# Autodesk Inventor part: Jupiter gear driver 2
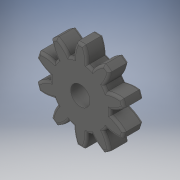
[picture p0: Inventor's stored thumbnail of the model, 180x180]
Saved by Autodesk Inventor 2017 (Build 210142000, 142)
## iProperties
Created: 2016-05
Part Number: Jupiter gear driver 2
Material: Generic
Document SubType Name: Modeling
Designer: Stan
Density: 1 g/cm^3
Appearance: Gray
Author: Stan
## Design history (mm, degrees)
sketch "Sketch1"
  geometry: A1 r 11.354 centre (-11.946, -5.594) between (-8.555, 5.242) and (-13.611, 5.638); A2 r 11.354 centre (-11.946, -5.594) between (-8.555, 5.242) and (-13.611, 5.638); A3 r 11.354 centre (1.628, 13.089) between (-9.568, 11.202) and (-7.629, 6.516); A4 r 11.354 centre (1.628, 13.089) between (-9.568, 11.202) and (-7.629, 6.516); A5 r 11.354 centre (-6.376, -11.547) between (-10.002, -0.787) and (-14.325, -3.439); A6 r 11.354 centre (-6.376, -11.547) between (-10.002, -0.787) and (-14.325, -3.439); A7 r 11.354 centre (-6.376, 11.547) between (-14.325, 3.439) and (-10.002, 0.787); A8 r 11.354 centre (-6.376, 11.547) between (-14.325, 3.439) and (-10.002, 0.787); A9 r 11.354 centre (1.628, -13.089) between (-7.629, -6.516) and (-9.568, -11.202); A10 r 11.354 centre (1.628, -13.089) between (-7.629, -6.516) and (-9.568, -11.202); A11 r 11.354 centre (-11.946, 5.594) between (-13.611, -5.638) and (-8.555, -5.242); A12 r 11.354 centre (-11.946, 5.594) between (-13.611, -5.638) and (-8.555, -5.242); A13 r 11.354 centre (9.011, -9.632) between (-2.342, -9.756) and (-1.156, -14.687); A14 r 11.354 centre (9.011, -9.632) between (-2.342, -9.756) and (-1.156, -14.687); A15 r 11.354 centre (-12.952, -2.496) between (-7.697, -12.561) and (-3.839, -9.269); A16 r 11.354 centre (-12.952, -2.496) between (-7.697, -12.561) and (-3.839, -9.269); A17 r 11.354 centre (12.952, -2.496) between (3.839, -9.269) and (7.697, -12.561); A18 r 11.354 centre (12.952, -2.496) between (3.839, -9.269) and (7.697, -12.561); A19 r 11.354 centre (-9.011, -9.632) between (1.156, -14.687) and (2.342, -9.756); A20 r 11.354 centre (-9.011, -9.632) between (1.156, -14.687) and (2.342, -9.756); A21 r 11.354 centre (11.946, 5.594) between (8.555, -5.242) and (13.611, -5.638); A22 r 11.354 centre (11.946, 5.594) between (8.555, -5.242) and (13.611, -5.638); A23 r 11.354 centre (-1.628, -13.089) between (9.568, -11.202) and (7.629, -6.516); A24 r 11.354 centre (-1.628, -13.089) between (9.568, -11.202) and (7.629, -6.516); A25 r 11.354 centre (6.376, 11.547) between (10.002, 0.787) and (14.325, 3.439); A26 r 11.354 centre (6.376, 11.547) between (10.002, 0.787) and (14.325, 3.439); A27 r 11.354 centre (6.376, -11.547) between (14.325, -3.439) and (10.002, -0.787); A28 r 11.354 centre (6.376, -11.547) between (14.325, -3.439) and (10.002, -0.787); A29 r 11.354 centre (-1.628, 13.089) between (7.629, 6.516) and (9.568, 11.202); A30 r 11.354 centre (-1.628, 13.089) between (7.629, 6.516) and (9.568, 11.202); A31 r 11.354 centre (11.946, -5.594) between (13.611, 5.638) and (8.555, 5.242); A32 r 11.354 centre (11.946, -5.594) between (13.611, 5.638) and (8.555, 5.242); A33 r 11.354 centre (-9.011, 9.632) between (2.342, 9.756) and (1.156, 14.687); A34 r 11.354 centre (-9.011, 9.632) between (2.342, 9.756) and (1.156, 14.687); A35 r 11.354 centre (12.952, 2.496) between (7.697, 12.561) and (3.839, 9.269); A36 r 11.354 centre (12.952, 2.496) between (7.697, 12.561) and (3.839, 9.269); A37 r 11.354 centre (1.628, 13.089) between (-9.568, 11.202) and (-7.629, 6.516); A38 r 11.354 centre (-11.946, -5.594) between (-8.555, 5.242) and (-13.611, 5.638); A39 r 11.354 centre (-6.376, 11.547) between (-14.325, 3.439) and (-10.002, 0.787); A40 r 11.354 centre (-6.376, -11.547) between (-10.002, -0.787) and (-14.325, -3.439); A41 r 11.354 centre (-11.946, 5.594) between (-13.611, -5.638) and (-8.555, -5.242); A42 r 11.354 centre (1.628, -13.089) between (-7.629, -6.516) and (-9.568, -11.202); A43 r 11.354 centre (-12.952, -2.496) between (-7.697, -12.561) and (-3.839, -9.269); A44 r 11.354 centre (9.011, -9.632) between (-2.342, -9.756) and (-1.156, -14.687); A45 r 11.354 centre (-9.011, -9.632) between (1.156, -14.687) and (2.342, -9.756); A46 r 11.354 centre (12.952, -2.496) between (3.839, -9.269) and (7.697, -12.561); A47 r 11.354 centre (-1.628, -13.089) between (9.568, -11.202) and (7.629, -6.516); A48 r 11.354 centre (11.946, 5.594) between (8.555, -5.242) and (13.611, -5.638); A49 r 11.354 centre (6.376, -11.547) between (14.325, -3.439) and (10.002, -0.787); A50 r 11.354 centre (6.376, 11.547) between (10.002, 0.787) and (14.325, 3.439); A51 r 11.354 centre (11.946, -5.594) between (13.611, 5.638) and (8.555, 5.242); A52 r 11.354 centre (-1.628, 13.089) between (7.629, 6.516) and (9.568, 11.202); A53 r 11.354 centre (12.952, 2.496) between (7.697, 12.561) and (3.839, 9.269); A54 r 11.354 centre (-9.011, 9.632) between (2.342, 9.756) and (1.156, 14.687); A55 r 11.354 centre (9.011, 9.632) between (-1.156, 14.687) and (-2.342, 9.756); A56 r 11.354 centre (-12.952, 2.496) between (-3.839, 9.269) and (-7.697, 12.561); A57 r 11.354 centre (-12.952, 2.496) between (-3.839, 9.269) and (-7.697, 12.561); A58 r 11.354 centre (-12.952, 2.496) between (-3.839, 9.269) and (-7.697, 12.561); A59 r 11.354 centre (9.011, 9.632) between (-1.156, 14.687) and (-2.342, 9.756); A60 r 11.354 centre (9.011, 9.632) between (-1.156, 14.687) and (-2.342, 9.756); A61 r 11.354 centre (1.628, 13.089) between (-9.568, 11.202) and (-7.629, 6.516); A62 r 11.354 centre (-12.952, 2.496) between (-3.839, 9.269) and (-7.697, 12.561); A63 r 11.354 centre (9.011, 9.632) between (-1.156, 14.687) and (-2.342, 9.756); A64 r 11.354 centre (-9.011, 9.632) between (2.342, 9.756) and (1.156, 14.687)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; 1 further point
  constraints: 160 point on circle, 80 centre point, 8 horizontal alignment, 8 vertical alignment, 224 other
extrude "Extrusion1" new body sketch "Sketch1" distance "d0" = 6.35; taper "d1" = 0 deg
sketch "Sketch2"
  geometry: C1 r 3.175 at (0, 0); 1 further point
  constraints: 1 centre point, 1 coincident
  dimensions: "d2" = 6.35 diameter of C1
extrude "Extrusion2" cut sketch "Sketch2" distance "d3" = 6.35; taper "d4" = 0 deg
fillet "Fillet1" dims "d5" = 0.79375
fillet "Fillet2" dims "d6" = 0.79375
body "Solid1"
